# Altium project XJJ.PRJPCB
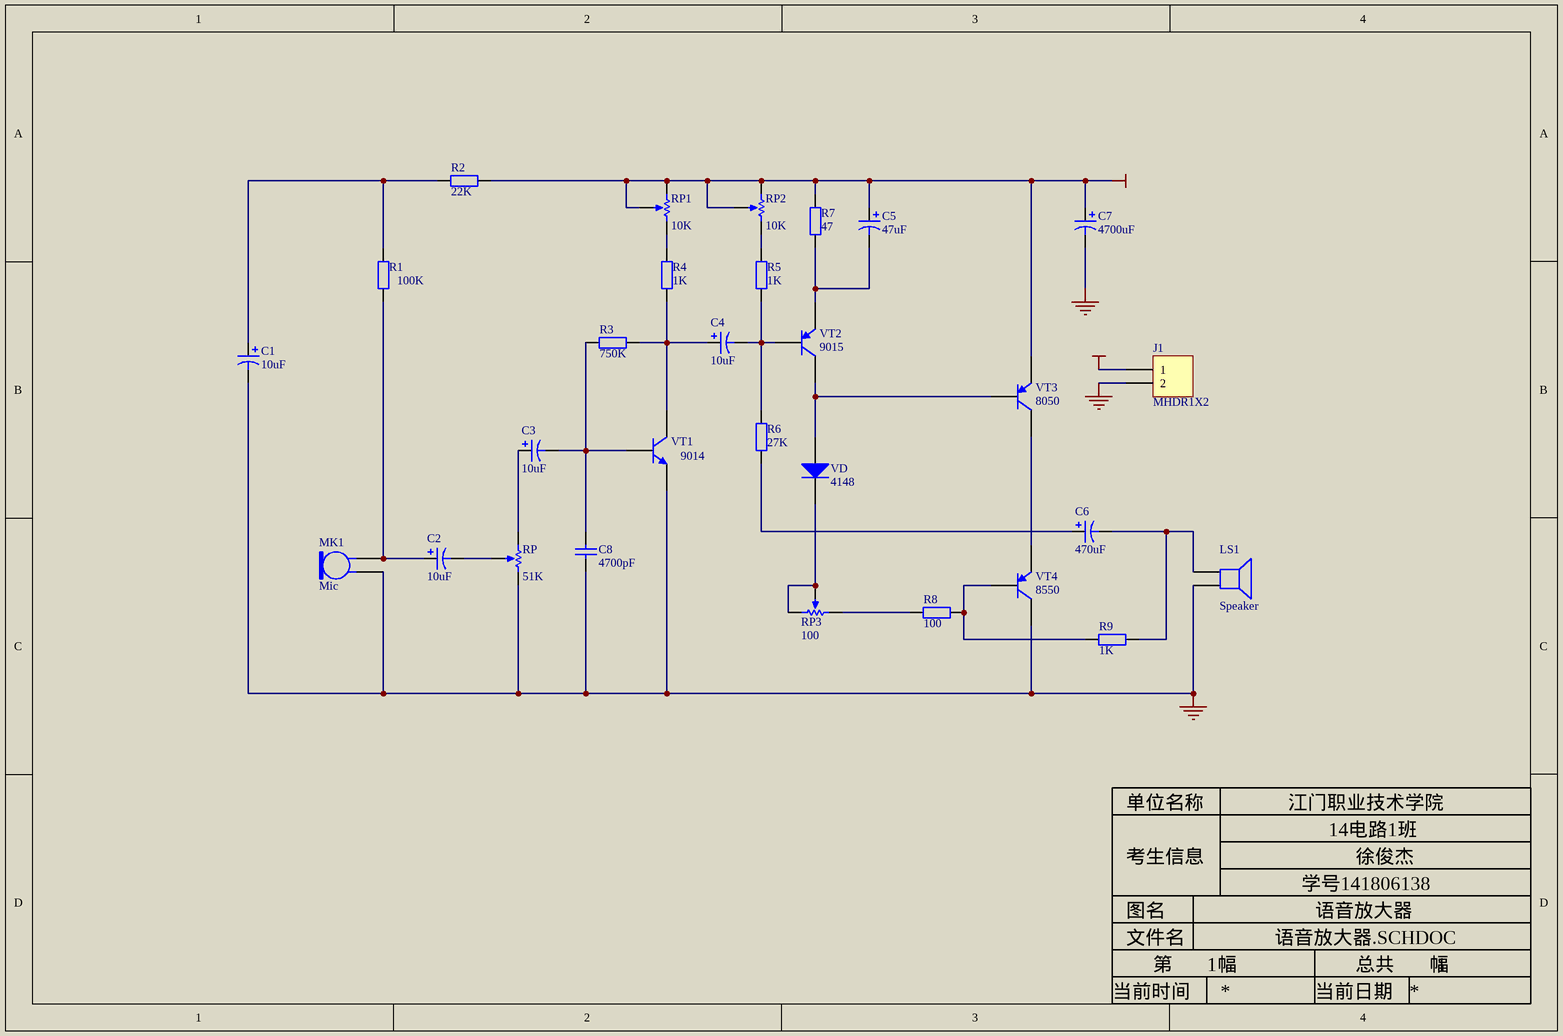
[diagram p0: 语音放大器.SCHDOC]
1 sheet, 29 parts. Net scope: global (net labels, ports and power ports of the same name join across sheets).
Board file: PCB2.PcbDoc

## Sheet 语音放大器.SCHDOC
size A4; Organization: 江门职业技术学院; Address1: 14电路1班; Address2: 徐俊杰; Address3: 学号141806138; Address4: 语音放大器; a: 1

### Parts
C1  value 10uF  [CAPPR5-5x5]  (hidden comment: Cap Pol1)
C2  value 10uF  [CAPPR5-5x5]  (hidden comment: Cap Pol1)
C3  value 10uF  [CAPPR5-5x5]  (hidden comment: Cap Pol1)
C4  value 10uF  [CAPPR5-5x5]  (hidden comment: Cap Pol1)
C5  value 47uF  [CAPPR5-5x5]  (hidden comment: Cap Pol1)
C6  value 470uF  [CAPPR5-5x5]  (hidden comment: Cap Pol1)
C7  value 4700uF  [CAPPR5-5x5]  (hidden comment: Cap Pol1)
C8  value 4700pF  [CAPR2.54-5.1x3.2]  (hidden comment: Cap)
J1  MHDR1X2  [HDR1X2]
LS1  Speaker  [PIN2]
MK1  Mic  [PIN2]
R1  value 100K  [AXIAL-0.3]  (hidden comment: Res2)
R2  value 22K  [AXIAL-0.3]  (hidden comment: Res2)
R3  value 750K  [AXIAL-0.3]  (hidden comment: Res2)
R4  value 1K  [AXIAL-0.3]  (hidden comment: Res2)
R5  value 1K  [AXIAL-0.3]  (hidden comment: Res2)
R6  value 27K  [AXIAL-0.3]  (hidden comment: Res2)
R7  value 47  [AXIAL-0.3]  (hidden comment: Res2)
R8  value 100  [AXIAL-0.3]  (hidden comment: Res2)
R9  value 1K  [AXIAL-0.3]  (hidden comment: Res2)
RP  value 51K  [RM065]  (hidden comment: RPot)
RP1  value 10K  [RM065]  (hidden comment: RPot)
RP2  value 10K  [RM065]  (hidden comment: RPot)
RP3  value 100  [RM065]  (hidden comment: RPot)
VD  4148  [DIODE-0.4]
VT1  9014  [BCY-W3/E4]
VT2  9015  [BCY-W3/E4]
VT3  8050  [BCY-W3/E4]
VT4  8550  [BCY-W3/E4]

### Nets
GND: C1.2 C7.2 C8.1 J1.2 LS1.2 MK1.1 RP.3(TAP) VT1.1(E) VT4.3(C)
VCC: C5.1 C7.1 J1.1 R2.2 R7.2 RP1.1(TOP) RP1.2(BOT) RP2.1(TOP) RP2.2(BOT) VT3.1(E)
NetC1_1: C1.1 R1.2 R2.1
NetC2_1: C2.1 MK1.2 R1.1
NetC2_2: C2.2 RP.2(BOT)
NetC3_1: C3.1 RP.1(TOP)
NetC3_2: C3.2 C8.2 R3.1 VT1.2(B)
NetC4_1: C4.1 R3.2 R4.1 VT1.3(C)
NetC4_2: C4.2 R5.1 R6.2 VT2.2(B)
NetC5_2: C5.2 R7.1 VT2.1(E)
NetC6_1: C6.1 R6.1
NetC6_2: C6.2 LS1.1 R9.2
NetR4_2: R4.2 RP1.3(TAP)
NetR5_2: R5.2 RP2.3(TAP)
NetR8_1: R8.1 RP3.1(TOP)
NetR8_2: R8.2 R9.1 VT4.2(B)
NetRP3_2: RP3.2(BOT) RP3.3(TAP) VD.2(K)
NetVD_1: VD.1(A) VT2.3(C) VT3.2(B)
NetVT3_3: VT3.3(C) VT4.1(E)

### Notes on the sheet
- 单位名称
- 考生信息
- 图名
- 文件名
- 第         幅
- 总共       幅
- 当前时间
- 当前日期

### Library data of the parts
C1-C7 = Cap Pol1: Polarized Capacitor (Radial)
C8 = Cap: Capacitor
J1 = Header 2: Header, 2-Pin
LS1 = Speaker: Loudspeaker
MK1 = Mic2: Microphone
R1-R9 = Res2: Resistor
RP RP1-RP3 = RPot: Potentiometer; Sim Note: Enter the Resistance value and the set point into parameter fields.; Set Position: 0.5
VD = Diode 1N4148: High Conductance Fast Diode
VT1 = 2N3904: NPN General Purpose Amplifier
VT2-VT4 = 2N3906: PNP General Purpose Amplifier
